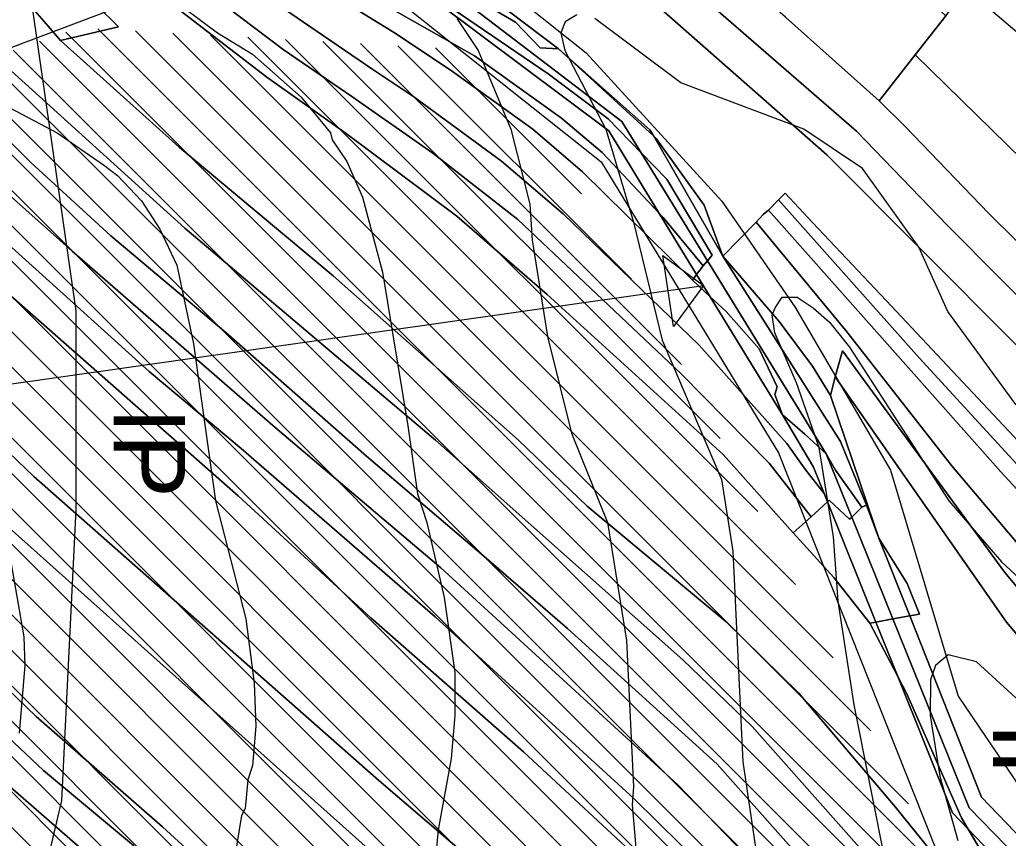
# Model space of a CAD drawing. Extents: x -510989 to -501240, y -1184665 to -1176098.
# Drawn here: x -505553.2 to -505276.8, y -1182106.3 to -1181877.4 of the extents above; entities that cross this region are included whole.
import ezdxf

# ---------------------------------------------------------------- set-up
doc = ezdxf.new("R2010")
doc.units = 0
for name, color, linetype in [('NAVRH_interakcni_prvky', 7, 'Continuous'), ('orna_puda', 7, 'Continuous'), ('ostatni_plocha_x_ostatni_komunikace', 7, 'Continuous'), ('STAV_erozne_ohrozene_plochy', 7, 'Continuous'), ('STAV_odtokove_linie', 7, 'Continuous'), ('STAV_vyrazne_udolnice', 7, 'Continuous'), ('vodni_plocha_x_vodni_tok_v_koryt_prir_n_upr', 7, 'Continuous'), ('vrstevnice_01', 7, 'Continuous'), ('vrstevnice_02', 7, 'Continuous')]:
    doc.layers.add(name, color=color, linetype=linetype)

msp = doc.modelspace()

# ---------------------------------------------------------------- linework, layer by layer
at = {"layer": 'NAVRH_interakcni_prvky'}
for points in [[(-505608.99, -1182282.38), (-505565.31, -1182197.02), (-505541.49, -1182095.78), (-505537.52, -1182014.39), (-505537.52, -1181958.81), (-505551.42, -1181861.54), (-505543.48, -1181770.22), (-505601.05, -1181698.76)], [(-505477.97, -1181847.64), (-505390.62, -1181917.12), (-505341, -1181998.51), (-505295.34, -1182113.64), (-505192.11, -1182200.99), (-505084.92, -1182282.38)]]:
    msp.add_lwpolyline(points, dxfattribs=at)
at = {"layer": 'orna_puda'}
for points in [[(-505519.74, -1181666.59), (-505508.87, -1181663.06), (-505436.24, -1181746.67), (-505407.73, -1181772.62), (-505294.24, -1181876.33), (-505302.86, -1181887.19), (-505312.86, -1181900.08), (-505339.06, -1181876.71), (-505374.7, -1181845.32), (-505416.23, -1181809.21), (-505441.36, -1181786.82), (-505449.1, -1181779.73), (-505469.88, -1181758.74), (-505476.89, -1181751.43), (-505531.87, -1181685.62), (-505540.76, -1181673.65)], [(-505567.93, -1181682.77), (-505552.51, -1181677.59), (-505498.97, -1181743.64), (-505474.97, -1181771.05), (-505460.17, -1181785.84), (-505427.45, -1181814.53), (-505319.25, -1181908.55), (-505293.76, -1181934.91), (-505233.92, -1181995.14), (-505145.97, -1182076.96), (-505126.19, -1182097.18), (-505131.28, -1182105.44), (-505151.3, -1182085.2), (-505248.6, -1181994.46), (-505327.51, -1181915.16), (-505374.61, -1181873.77), (-505471.42, -1181794.36), (-505487.88, -1181779.75), (-505511, -1181753.67), (-505546.09, -1181711.4)], [(-505645.06, -1181709.14), (-505630.33, -1181704), (-505607.36, -1181739.3), (-505581.79, -1181780.35), (-505558.96, -1181811.1), (-505514.25, -1181867.52), (-505531.74, -1181873.34), (-505525.62, -1181879.39), (-505541.83, -1181883.21), (-505546.41, -1181877.85), (-505568.04, -1181853.19), (-505576.73, -1181845.92), (-505581.16, -1181840.91), (-505588.32, -1181829.06), (-505610.78, -1181797.53), (-505641.63, -1181746.38), (-505660.24, -1181714.54)], [(-505473.72, -1181862.1), (-505452.56, -1181872.44), (-505426.03, -1181887.45), (-505401.77, -1181904.93), (-505390.39, -1181914.52), (-505374.47, -1181931.42), (-505363.93, -1181948.67), (-505365.1, -1181950.24), (-505395.9, -1181919.93), (-505409.72, -1181908.03), (-505432.85, -1181891.41), (-505448.68, -1181880.86), (-505477.39, -1181863.18)], [(-505468.05, -1181861.22), (-505452.66, -1181865.28), (-505436.96, -1181872.23), (-505388.53, -1181908.42), (-505374.47, -1181931.42), (-505390.39, -1181914.52), (-505401.77, -1181904.93), (-505426.03, -1181887.45), (-505452.56, -1181872.44), (-505473.72, -1181862.1), (-505469.56, -1181860.93)], [(-505294.24, -1181876.33), (-505282.63, -1181861.56), (-505226.01, -1181917.52), (-505156.75, -1181981.55), (-505092.62, -1182042.63), (-505109.95, -1182070.79), (-505121, -1182060.28), (-505151.91, -1182031.8), (-505229.82, -1181958.67), (-505302.86, -1181887.19)], [(-505302.86, -1181887.19), (-505229.82, -1181958.67), (-505151.91, -1182031.8), (-505121, -1182060.28), (-505109.95, -1182070.79), (-505120.17, -1182087.4), (-505123.25, -1182084.13), (-505160.44, -1182047.5), (-505233.93, -1181979.37), (-505282.34, -1181931.52), (-505305.54, -1181907.33), (-505312.86, -1181900.08)], [(-505375.92, -1181909.99), (-505375.25, -1181910.61), (-505361.8, -1181929.25), (-505356.61, -1181943.5)], [(-505339.14, -1181925.86), (-505331.49, -1181934.08), (-505310.93, -1181955.96), (-505268.16, -1182001.48), (-505249.53, -1182020.18), (-505153.49, -1182107.08), (-505140.34, -1182120.18), (-505143.41, -1182125.16), (-505172.14, -1182098.63), (-505205.31, -1182068.09), (-505268.09, -1182008.54), (-505301.67, -1181971.92), (-505341.02, -1181927.75)], [(-505341.02, -1181927.75), (-505301.67, -1181971.92), (-505268.09, -1182008.54), (-505205.31, -1182068.09), (-505172.14, -1182098.63), (-505143.41, -1182125.16), (-505146.08, -1182129.51), (-505167.23, -1182110.12), (-505208.08, -1182073.61), (-505257.36, -1182027.15), (-505278.84, -1182003.86), (-505343.84, -1181930.61)], [(-505345.3, -1181931.85), (-505343.84, -1181930.61), (-505278.84, -1182003.86), (-505257.36, -1182027.15), (-505208.08, -1182073.61), (-505167.23, -1182110.12), (-505146.08, -1182129.51), (-505151.91, -1182138.98), (-505217.21, -1182081.69), (-505242.35, -1182057.55), (-505267.43, -1182031.96), (-505292.64, -1182002.06), (-505321.57, -1181965.12), (-505321.82, -1181964.8), (-505347.28, -1181933.98)], [(-505347.28, -1181933.98), (-505321.82, -1181964.8), (-505321.57, -1181965.12), (-505292.64, -1182002.06), (-505267.43, -1182031.96), (-505242.35, -1182057.55), (-505217.21, -1182081.69), (-505151.91, -1182138.98), (-505157.56, -1182148.15), (-505215.94, -1182098.45), (-505246.35, -1182067.52), (-505264.28, -1182048.04), (-505277.73, -1182032.03), (-505323.14, -1181970.04), (-505325.21, -1181977.28), (-505326.47, -1181982.51), (-505331.51, -1181974.26), (-505340.82, -1181961.79), (-505356.61, -1181943.5)], [(-505356.61, -1181943.5), (-505340.82, -1181961.79), (-505331.51, -1181974.26), (-505326.47, -1181982.51), (-505316.12, -1182013.04), (-505316.46, -1182013.18), (-505323.7, -1181995.32)], [(-505365.1, -1181950.24), (-505363.93, -1181948.67), (-505360.15, -1181954.85)], [(-505325.21, -1181977.28), (-505323.14, -1181970.04), (-505277.73, -1182032.03), (-505264.28, -1182048.04), (-505246.35, -1182067.52), (-505215.94, -1182098.45), (-505157.56, -1182148.15), (-505162.84, -1182156.74), (-505167.04, -1182153.21), (-505211.27, -1182118.01), (-505245.02, -1182084.01), (-505277.31, -1182045.9), (-505321.5, -1181982.6)], [(-505326.47, -1181982.51), (-505325.21, -1181977.28), (-505321.5, -1181982.6), (-505277.31, -1182045.9), (-505245.02, -1182084.01), (-505211.27, -1182118.01), (-505167.04, -1182153.21), (-505162.84, -1182156.74), (-505171.16, -1182170.25), (-505178.64, -1182182.4), (-505181.95, -1182187.8), (-505198.66, -1182175.96), (-505218.28, -1182163.42), (-505253.16, -1182127.19), (-505259.03, -1182115.11), (-505267.67, -1182107.25), (-505270.34, -1182109.35), (-505284.27, -1182094.87), (-505304.35, -1182044.13), (-505301.63, -1182043.63), (-505305.03, -1182035.12), (-505312.96, -1182022.37), (-505316.12, -1182013.04)], [(-505331.94, -1182016.42), (-505327.34, -1182012.21), (-505313.82, -1182045.87), (-505315.51, -1182046.18), (-505325.56, -1182033.42), (-505336.89, -1182020.96)], [(-505316.46, -1182013.18), (-505316.12, -1182013.04), (-505312.96, -1182022.37)], [(-505312.96, -1182022.37), (-505305.03, -1182035.12), (-505301.63, -1182043.63), (-505304.35, -1182044.13)], [(-505313.82, -1182045.87), (-505307.69, -1182061.13), (-505315.51, -1182046.18)], [(-505288.01, -1182103.77), (-505277.34, -1182114.86), (-505280.14, -1182117.06)]]:
    msp.add_lwpolyline(points, close=True, dxfattribs=at)
for points in [[(-505572.34, -1181774.68), (-505551.57, -1181801.41), (-505501.85, -1181863.87), (-505499.45, -1181870.62), (-505479.62, -1181885.73), (-505460.4, -1181898.83), (-505437.74, -1181914.7), (-505413.98, -1181933.27), (-505368.28, -1181976.43), (-505343.69, -1182001.41), (-505331.94, -1182016.42), (-505336.89, -1182020.96), (-505356.56, -1181998.96), (-505405.71, -1181954.22), (-505430.96, -1181932.36), (-505462, -1181909.24), (-505484.12, -1181893.43), (-505509.52, -1181873.93), (-505514.25, -1181867.52), (-505558.96, -1181811.1)], [(-505339.06, -1181876.71), (-505312.86, -1181900.08), (-505305.54, -1181907.33), (-505282.34, -1181931.52), (-505233.93, -1181979.37), (-505160.44, -1182047.5), (-505123.25, -1182084.13), (-505120.17, -1182087.4), (-505123.23, -1182092.36), (-505126.19, -1182097.18), (-505145.97, -1182076.96), (-505233.92, -1181995.14), (-505293.76, -1181934.91), (-505319.25, -1181908.55), (-505427.45, -1181814.53)], [(-505568.04, -1181853.19), (-505546.41, -1181877.85), (-505541.83, -1181883.21), (-505508.63, -1181913.03), (-505465.61, -1181948.98), (-505413.77, -1181995.02), (-505394.59, -1182013.48), (-505355.64, -1182045.79), (-505335.45, -1182065.69), (-505308.28, -1182097.68), (-505287.99, -1182122.8)], [(-505374.61, -1181873.77), (-505327.51, -1181915.16), (-505248.6, -1181994.46), (-505151.3, -1182085.2), (-505131.28, -1182105.44), (-505140.34, -1182120.18), (-505153.49, -1182107.08), (-505249.53, -1182020.18), (-505268.16, -1182001.48), (-505310.93, -1181955.96), (-505331.49, -1181934.08), (-505339.14, -1181925.86), (-505341.02, -1181927.75), (-505343.84, -1181930.61), (-505345.3, -1181931.85), (-505347.28, -1181933.98), (-505356.61, -1181943.5), (-505361.8, -1181929.25), (-505375.25, -1181910.61), (-505375.92, -1181909.99), (-505376.99, -1181908.14), (-505402.58, -1181885.53), (-505438.7, -1181858.11)], [(-505477.39, -1181863.18), (-505448.68, -1181880.86), (-505432.85, -1181891.41), (-505409.72, -1181908.03), (-505395.9, -1181919.93), (-505365.1, -1181950.24), (-505360.15, -1181954.85), (-505339.92, -1181987.93), (-505331.23, -1182002.54), (-505328.26, -1182009.92), (-505333.35, -1182003.39), (-505338.73, -1181995.88), (-505363.24, -1181968.45), (-505401.25, -1181931.67), (-505418.52, -1181916.94), (-505443, -1181898.93), (-505454.5, -1181891.31), (-505489.16, -1181867.5)], [(-505489.16, -1181867.5), (-505454.5, -1181891.31), (-505443, -1181898.93), (-505418.52, -1181916.94), (-505401.25, -1181931.67), (-505363.24, -1181968.45), (-505338.73, -1181995.88), (-505333.35, -1182003.39), (-505328.26, -1182009.92), (-505327.34, -1182012.21), (-505331.94, -1182016.42), (-505343.69, -1182001.41), (-505368.28, -1181976.43), (-505413.98, -1181933.27), (-505437.74, -1181914.7), (-505460.4, -1181898.83), (-505479.62, -1181885.73), (-505499.45, -1181870.62)], [(-505287.99, -1182122.8), (-505308.28, -1182097.68), (-505335.45, -1182065.69), (-505355.64, -1182045.79), (-505394.59, -1182013.48), (-505413.77, -1181995.02), (-505465.61, -1181948.98), (-505508.63, -1181913.03), (-505541.83, -1181883.21), (-505525.62, -1181879.39), (-505531.74, -1181873.34)], [(-505509.52, -1181873.93), (-505484.12, -1181893.43), (-505462, -1181909.24), (-505430.96, -1181932.36), (-505405.71, -1181954.22), (-505356.56, -1181998.96), (-505336.89, -1182020.96), (-505325.56, -1182033.42), (-505315.51, -1182046.18), (-505307.69, -1182061.13), (-505292.37, -1182099.24), (-505288.01, -1182103.77), (-505280.14, -1182117.06)], [(-505301.62, -1182127.85), (-505348.44, -1182075.1), (-505367.81, -1182056.44), (-505436.93, -1181994.95), (-505507.07, -1181935.7), (-505555.65, -1181891.64)], [(-505555.65, -1181891.64), (-505507.07, -1181935.7), (-505436.93, -1181994.95), (-505367.81, -1182056.44), (-505348.44, -1182075.1), (-505301.62, -1182127.85)], [(-505573.04, -1181894.67), (-505550.18, -1181917.35), (-505527.82, -1181937.83), (-505495.62, -1181964.87), (-505456.25, -1181999.44), (-505422.81, -1182027.98), (-505400.01, -1182047.67), (-505358.23, -1182085.64), (-505328.68, -1182118.88)], [(-505328.68, -1182118.88), (-505358.23, -1182085.64), (-505400.01, -1182047.67), (-505422.81, -1182027.98), (-505456.25, -1181999.44), (-505495.62, -1181964.87), (-505527.82, -1181937.83), (-505550.18, -1181917.35), (-505573.04, -1181894.67)], [(-505567.25, -1181916.64), (-505538.57, -1181942.08), (-505481.82, -1181991.47), (-505435.51, -1182030.72), (-505369.15, -1182091.43), (-505337.03, -1182124.65)], [(-505337.03, -1182124.65), (-505369.15, -1182091.43), (-505435.51, -1182030.72), (-505481.82, -1181991.47), (-505538.57, -1181942.08), (-505567.25, -1181916.64)], [(-505576.76, -1181921.98), (-505517.02, -1181975.79), (-505491.29, -1181997.29), (-505437.08, -1182044.44), (-505381.51, -1182095.2), (-505355.45, -1182120.85)], [(-505355.45, -1182120.85), (-505381.51, -1182095.2), (-505437.08, -1182044.44), (-505491.29, -1181997.29), (-505517.02, -1181975.79), (-505576.76, -1181921.98)], [(-505569.87, -1181942.31), (-505492.15, -1182010.58), (-505455.06, -1182044.65), (-505412.33, -1182082.21), (-505379.96, -1182112.3)], [(-505379.96, -1182112.3), (-505412.33, -1182082.21), (-505455.06, -1182044.65), (-505492.15, -1182010.58), (-505569.87, -1181942.31)], [(-505425.83, -1182113.33), (-505452.81, -1182090.24), (-505549.33, -1182005.12), (-505584.61, -1181971.35)], [(-505584.61, -1181971.35), (-505549.33, -1182005.12), (-505452.81, -1182090.24), (-505425.83, -1182113.33), (-505411.76, -1182126.27), (-505367.44, -1182171.49), (-505349.75, -1182191.77), (-505323.63, -1182222.02), (-505283.06, -1182271.94), (-505258.09, -1182307.38), (-505257.86, -1182307.7), (-505226.26, -1182351.65), (-505241.61, -1182355.59), (-505271.5, -1182315.96), (-505294.02, -1182284.84), (-505330.4, -1182239.7), (-505379.76, -1182182.4), (-505425.42, -1182136.45), (-505449.63, -1182114.77), (-505566.1, -1182010.76)], [(-505566.1, -1182010.76), (-505449.63, -1182114.77), (-505425.42, -1182136.45), (-505379.76, -1182182.4), (-505330.4, -1182239.7), (-505294.02, -1182284.84), (-505271.5, -1182315.96), (-505241.61, -1182355.59), (-505266.95, -1182362.08), (-505275.95, -1182364.1), (-505298.69, -1182333.35), (-505352.13, -1182266.89), (-505402.08, -1182210.88), (-505426.3, -1182185.24), (-505472.43, -1182140.66), (-505513.32, -1182103.17), (-505548.69, -1182072.33), (-505575.74, -1182046.26)], [(-505575.74, -1182046.26), (-505548.69, -1182072.33), (-505513.32, -1182103.17), (-505472.43, -1182140.66), (-505426.3, -1182185.24), (-505402.08, -1182210.88), (-505352.13, -1182266.89), (-505298.69, -1182333.35), (-505275.95, -1182364.1), (-505285.64, -1182366.68), (-505297.41, -1182349.58), (-505324.32, -1182317.98), (-505360.11, -1182274.25), (-505392.22, -1182237.49), (-505428.43, -1182199.01), (-505477.26, -1182151.05), (-505521.45, -1182108.4), (-505546.57, -1182087.4), (-505591.18, -1182045.46)], [(-505591.18, -1182045.46), (-505546.57, -1182087.4), (-505521.45, -1182108.4), (-505477.26, -1182151.05), (-505428.43, -1182199.01), (-505392.22, -1182237.49), (-505360.11, -1182274.25), (-505324.32, -1182317.98), (-505297.41, -1182349.58), (-505285.64, -1182366.68), (-505296.59, -1182369.07), (-505309.57, -1182350.56), (-505365.73, -1182282.9), (-505427.03, -1182215.92), (-505500.72, -1182142.35), (-505529.84, -1182114.76), (-505588.6, -1182063.62)], [(-505588.6, -1182063.62), (-505529.84, -1182114.76), (-505500.72, -1182142.35), (-505427.03, -1182215.92), (-505365.73, -1182282.9), (-505309.57, -1182350.56), (-505296.59, -1182369.07), (-505307.29, -1182369.64), (-505313.59, -1182369.95), (-505328.19, -1182350.29), (-505373.76, -1182297.21), (-505400.25, -1182266.18), (-505430.38, -1182233.94), (-505477.83, -1182186.76), (-505528.18, -1182137.53), (-505577.6, -1182094)]]:
    msp.add_lwpolyline(points, dxfattribs=at)
at = {"layer": 'ostatni_plocha_x_ostatni_komunikace'}
for points in [[(-505473.57, -1181836.02), (-505458.92, -1181852.15), (-505442.91, -1181861.51), (-505384.83, -1181905.86), (-505379.47, -1181914.58), (-505388.68, -1181905.11), (-505405.46, -1181892.51), (-505432.06, -1181874.4), (-505436.96, -1181872.23), (-505458.6, -1181856.06), (-505475.57, -1181840.04)], [(-505432.06, -1181874.4), (-505405.46, -1181892.51), (-505388.68, -1181905.11), (-505379.47, -1181914.58), (-505360.9, -1181944.8), (-505362.1, -1181946.22), (-505373.3, -1181932.66), (-505374.47, -1181931.42), (-505388.53, -1181908.42), (-505436.96, -1181872.23)], [(-505373.3, -1181932.66), (-505362.1, -1181946.22), (-505363.93, -1181948.67), (-505374.47, -1181931.42)], [(-505362.1, -1181946.22), (-505360.9, -1181944.8), (-505327.69, -1181998.85), (-505333.64, -1181993.33), (-505339.92, -1181987.93), (-505342.07, -1181982.26), (-505341.37, -1181980.06), (-505346.41, -1181969.42), (-505355.66, -1181959.03), (-505360.15, -1181954.85), (-505363.93, -1181948.67)], [(-505360.15, -1181954.85), (-505355.66, -1181959.03), (-505346.41, -1181969.42), (-505341.37, -1181980.06), (-505342.07, -1181982.26), (-505339.92, -1181987.93)], [(-505333.64, -1181993.33), (-505327.69, -1181998.85), (-505320.55, -1182016.51), (-505321.17, -1182017.13), (-505326.84, -1182011.75), (-505327.34, -1182012.21), (-505328.26, -1182009.92), (-505331.23, -1182002.54), (-505339.92, -1181987.93)], [(-505327.34, -1182012.21), (-505326.84, -1182011.75), (-505321.17, -1182017.13), (-505320.55, -1182016.51), (-505309.04, -1182044.99), (-505313.82, -1182045.87)], [(-505309.04, -1182044.99), (-505287.69, -1182097.86), (-505273.82, -1182112.09), (-505277.34, -1182114.86), (-505288.01, -1182103.77), (-505289.87, -1182100.63), (-505305.16, -1182065.96), (-505307.69, -1182061.13), (-505313.82, -1182045.87)], [(-505307.69, -1182061.13), (-505305.16, -1182065.96), (-505289.87, -1182100.63), (-505288.01, -1182103.77), (-505292.37, -1182099.24)]]:
    msp.add_lwpolyline(points, close=True, dxfattribs=at)
at = {"layer": 'STAV_erozne_ohrozene_plochy'}
for p, q in [((-505531.4, -1181879.92), (-505294.12, -1182117.2)), ((-505540.39, -1181880.82), (-505283.57, -1182137.64)), ((-505520.91, -1181880.51), (-505304.67, -1182096.75)), ((-505510.42, -1181881.1), (-505315.21, -1182076.3)), ((-505499.93, -1181881.69), (-505325.76, -1182055.86)), ((-505489.44, -1181882.28), (-505336.31, -1182035.41)), ((-505478.95, -1181882.87), (-505346.86, -1182014.96)), ((-505547.76, -1181883.35), (-505144.55, -1182286.57)), ((-505468.46, -1181883.46), (-505357.4, -1181994.52)), ((-505457.97, -1181884.06), (-505368.15, -1181973.87)), ((-505447.48, -1181884.65), (-505382.14, -1181949.99)), ((-505436.99, -1181885.24), (-505396.13, -1181926.1)), ((-505562.5, -1181888.41), (-505156.57, -1182294.35)), ((-505555.13, -1181885.88), (-505150.56, -1182290.46)), ((-505569.88, -1181890.94), (-505162.58, -1182298.24)), ((-505577.25, -1181893.47), (-505168.58, -1182302.13)), ((-505584.62, -1181896), (-505174.59, -1182306.02)), ((-505591.99, -1181898.53), (-505180.6, -1182309.91)), ((-505599.36, -1181901.05), (-505186.61, -1182313.8)), ((-505606.73, -1181903.58), (-505192.62, -1182317.69)), ((-505614.1, -1181906.11), (-505198.63, -1182321.58)), ((-505621.47, -1181908.64), (-505204.64, -1182325.47)), ((-505628.84, -1181911.17), (-505210.65, -1182329.36)), ((-505636.21, -1181913.7), (-505216.66, -1182333.25)), ((-505650.95, -1181918.76), (-505228.68, -1182341.03)), ((-505643.58, -1181916.23), (-505222.67, -1182337.14)), ((-505658.32, -1181921.29), (-505235.89, -1182343.71)), ((-505665.69, -1181923.81), (-505244.24, -1182345.26)), ((-505673.06, -1181926.34), (-505252.6, -1182346.81)), ((-505680.44, -1181928.87), (-505260.95, -1182348.36)), ((-505687.81, -1181931.4), (-505269.3, -1182349.91)), ((-505695.18, -1181933.93), (-505277.65, -1182351.46)), ((-505702.55, -1181936.46), (-505286, -1182353.01)), ((-505709.92, -1181938.99), (-505294.35, -1182354.56)), ((-505717.29, -1181941.52), (-505302.7, -1182356.11))]:
    msp.add_line(p, q, dxfattribs=at)
at = {"layer": 'STAV_odtokove_linie'}
msp.add_line((-505776.39, -1182010.5), (-505362.04, -1181951.76), dxfattribs=at)
msp.add_lwpolyline([(-505373.43, -1181943.38), (-505362.04, -1181951.76), (-505370.42, -1181963.15)], close=True, dxfattribs=at)
at = {"layer": 'STAV_vyrazne_udolnice'}
for points in [[(-505486.28, -1181776.97), (-505446.89, -1181838.83), (-505419.46, -1181866.96), (-505394.84, -1181886.64), (-505356.86, -1181928.12), (-505336.47, -1181957.65), (-505309.74, -1182003.35), (-505290.75, -1182066.62), (-505259.8, -1182112.32), (-505235.89, -1182136.93), (-505145.86, -1182211.45), (-505082.56, -1182255.04), (-505023.48, -1182296.52)], [(-505479.85, -1181863.64), (-505528.38, -1181874.89), (-505582.54, -1181895.28), (-505631.07, -1181912.86), (-505672.56, -1181926.92), (-505720.39, -1181954.34), (-505737.97, -1181965.58)]]:
    msp.add_lwpolyline(points, dxfattribs=at)
at = {"layer": 'vodni_plocha_x_vodni_tok_v_koryt_prir_n_upr'}
for points in [[(-505473.57, -1181836.02), (-505471.72, -1181833.5), (-505438.7, -1181858.11), (-505402.58, -1181885.53), (-505407.68, -1181885.25), (-505414.59, -1181878.08), (-505442.91, -1181861.51), (-505456.42, -1181851.2)], [(-505442.91, -1181861.51), (-505414.59, -1181878.08), (-505407.68, -1181885.25), (-505402.58, -1181885.53), (-505375.92, -1181909.99), (-505356.61, -1181943.5), (-505323.7, -1181995.32), (-505316.46, -1182013.18), (-505317.77, -1182013.73), (-505325.14, -1182003.39), (-505327.69, -1181998.85), (-505360.9, -1181944.8), (-505359.55, -1181943.2), (-505372.25, -1181922.01), (-505379.47, -1181914.58), (-505384.83, -1181905.86)], [(-505402.58, -1181885.53), (-505376.99, -1181908.14), (-505375.92, -1181909.99)], [(-505372.25, -1181922.01), (-505359.55, -1181943.2), (-505360.9, -1181944.8), (-505379.47, -1181914.58)], [(-505325.14, -1182003.39), (-505317.77, -1182013.73), (-505320.55, -1182016.51), (-505327.69, -1181998.85)], [(-505317.77, -1182013.73), (-505316.46, -1182013.18), (-505312.96, -1182022.37), (-505304.35, -1182044.13), (-505309.04, -1182044.99), (-505320.55, -1182016.51)], [(-505304.35, -1182044.13), (-505284.27, -1182094.87), (-505270.34, -1182109.35), (-505273.82, -1182112.09), (-505287.69, -1182097.86), (-505309.04, -1182044.99)]]:
    msp.add_lwpolyline(points, close=True, dxfattribs=at)
at = {"layer": 'vrstevnice_01'}
for points in [[(-505038.31, -1181871), (-505065.41, -1181897), (-505079.5, -1181912), (-505095.41, -1181925), (-505118.81, -1181935), (-505129.19, -1181938), (-505158.09, -1181944), (-505194.69, -1181945), (-505212.69, -1181941), (-505226.31, -1181935), (-505237.5, -1181926), (-505250.91, -1181910), (-505270.69, -1181884), (-505284.81, -1181872)], [(-505431, -1181877), (-505425, -1181886), (-505415.91, -1181908), (-505410.59, -1181929), (-505409.91, -1181939), (-505405.69, -1181966), (-505398.91, -1181993), (-505388.91, -1182018), (-505383.59, -1182051), (-505381.59, -1182092), (-505382, -1182097), (-505380.91, -1182109)], [(-505556, -1181902), (-505542.81, -1181909), (-505529.81, -1181918), (-505525.91, -1181921), (-505519.19, -1181928), (-505514.09, -1181936), (-505509.31, -1181946), (-505504.69, -1181968), (-505498.5, -1182012), (-505490, -1182045), (-505487.69, -1182063), (-505487.19, -1182075), (-505488.19, -1182086), (-505489.5, -1182090), (-505490.19, -1182098), (-505491.19, -1182100), (-505493.19, -1182112)], [(-505310.91, -1182114), (-505319.91, -1182069), (-505324.31, -1182040), (-505325.69, -1182022), (-505329.69, -1181997), (-505336, -1181979), (-505342.09, -1181965), (-505342.81, -1181960), (-505342, -1181958), (-505340, -1181955), (-505335.81, -1181955), (-505331.31, -1181958), (-505326.81, -1181962), (-505321.19, -1181969), (-505293.41, -1182012), (-505278.69, -1182029), (-505263.59, -1182043), (-505245.69, -1182055), (-505186.91, -1182088), (-505179.09, -1182090), (-505153.81, -1182093), (-505138.5, -1182093), (-505116, -1182091)]]:
    msp.add_lwpolyline(points, dxfattribs=at)
at = {"layer": 'vrstevnice_02'}
for points in [[(-505507.41, -1181874), (-505497.91, -1181881), (-505488.19, -1181887), (-505474.5, -1181899), (-505466.31, -1181909), (-505465.91, -1181911), (-505461.81, -1181917), (-505457.41, -1181927), (-505451.81, -1181948), (-505444.69, -1181991), (-505442, -1182010), (-505439.41, -1182018), (-505434.59, -1182039), (-505431.59, -1182060), (-505431.59, -1182072), (-505432.59, -1182084), (-505436.19, -1182104), (-505439.19, -1182136)], [(-505397.41, -1181876), (-505400.69, -1181878), (-505401.91, -1181881), (-505400.81, -1181886), (-505389.31, -1181908), (-505381.59, -1181934), (-505373.59, -1181967), (-505357, -1182006), (-505353.81, -1182026), (-505351, -1182085), (-505346.69, -1182114)], [(-505124.31, -1182023), (-505147.69, -1182026), (-505161.81, -1182025), (-505217.91, -1182017), (-505237.59, -1182011), (-505251.09, -1182005), (-505260.19, -1181999), (-505274.69, -1181985), (-505293.69, -1181959), (-505301.81, -1181941), (-505317.59, -1181919), (-505333.91, -1181908), (-505368.31, -1181895), (-505392.41, -1181877)], [(-505564.69, -1181978), (-505552.09, -1182050), (-505551.81, -1182058), (-505553.41, -1182077)], [(-505194.19, -1182124), (-505227.81, -1182099), (-505260.5, -1182080), (-505285.69, -1182057), (-505293.59, -1182055), (-505297.09, -1182058), (-505298.5, -1182062), (-505298.59, -1182072), (-505295.91, -1182089), (-505290.91, -1182107)]]:
    msp.add_lwpolyline(points, dxfattribs=at)

# ---------------------------------------------------------------- texts
at = {"layer": 'NAVRH_interakcni_prvky'}
for p in [(-505527, -1181985.81), (-505281.07, -1182074.11)]:
    msp.add_text('IP', height=20, rotation=270, dxfattribs=at).set_placement(p)

doc.saveas('drawing.dxf')
